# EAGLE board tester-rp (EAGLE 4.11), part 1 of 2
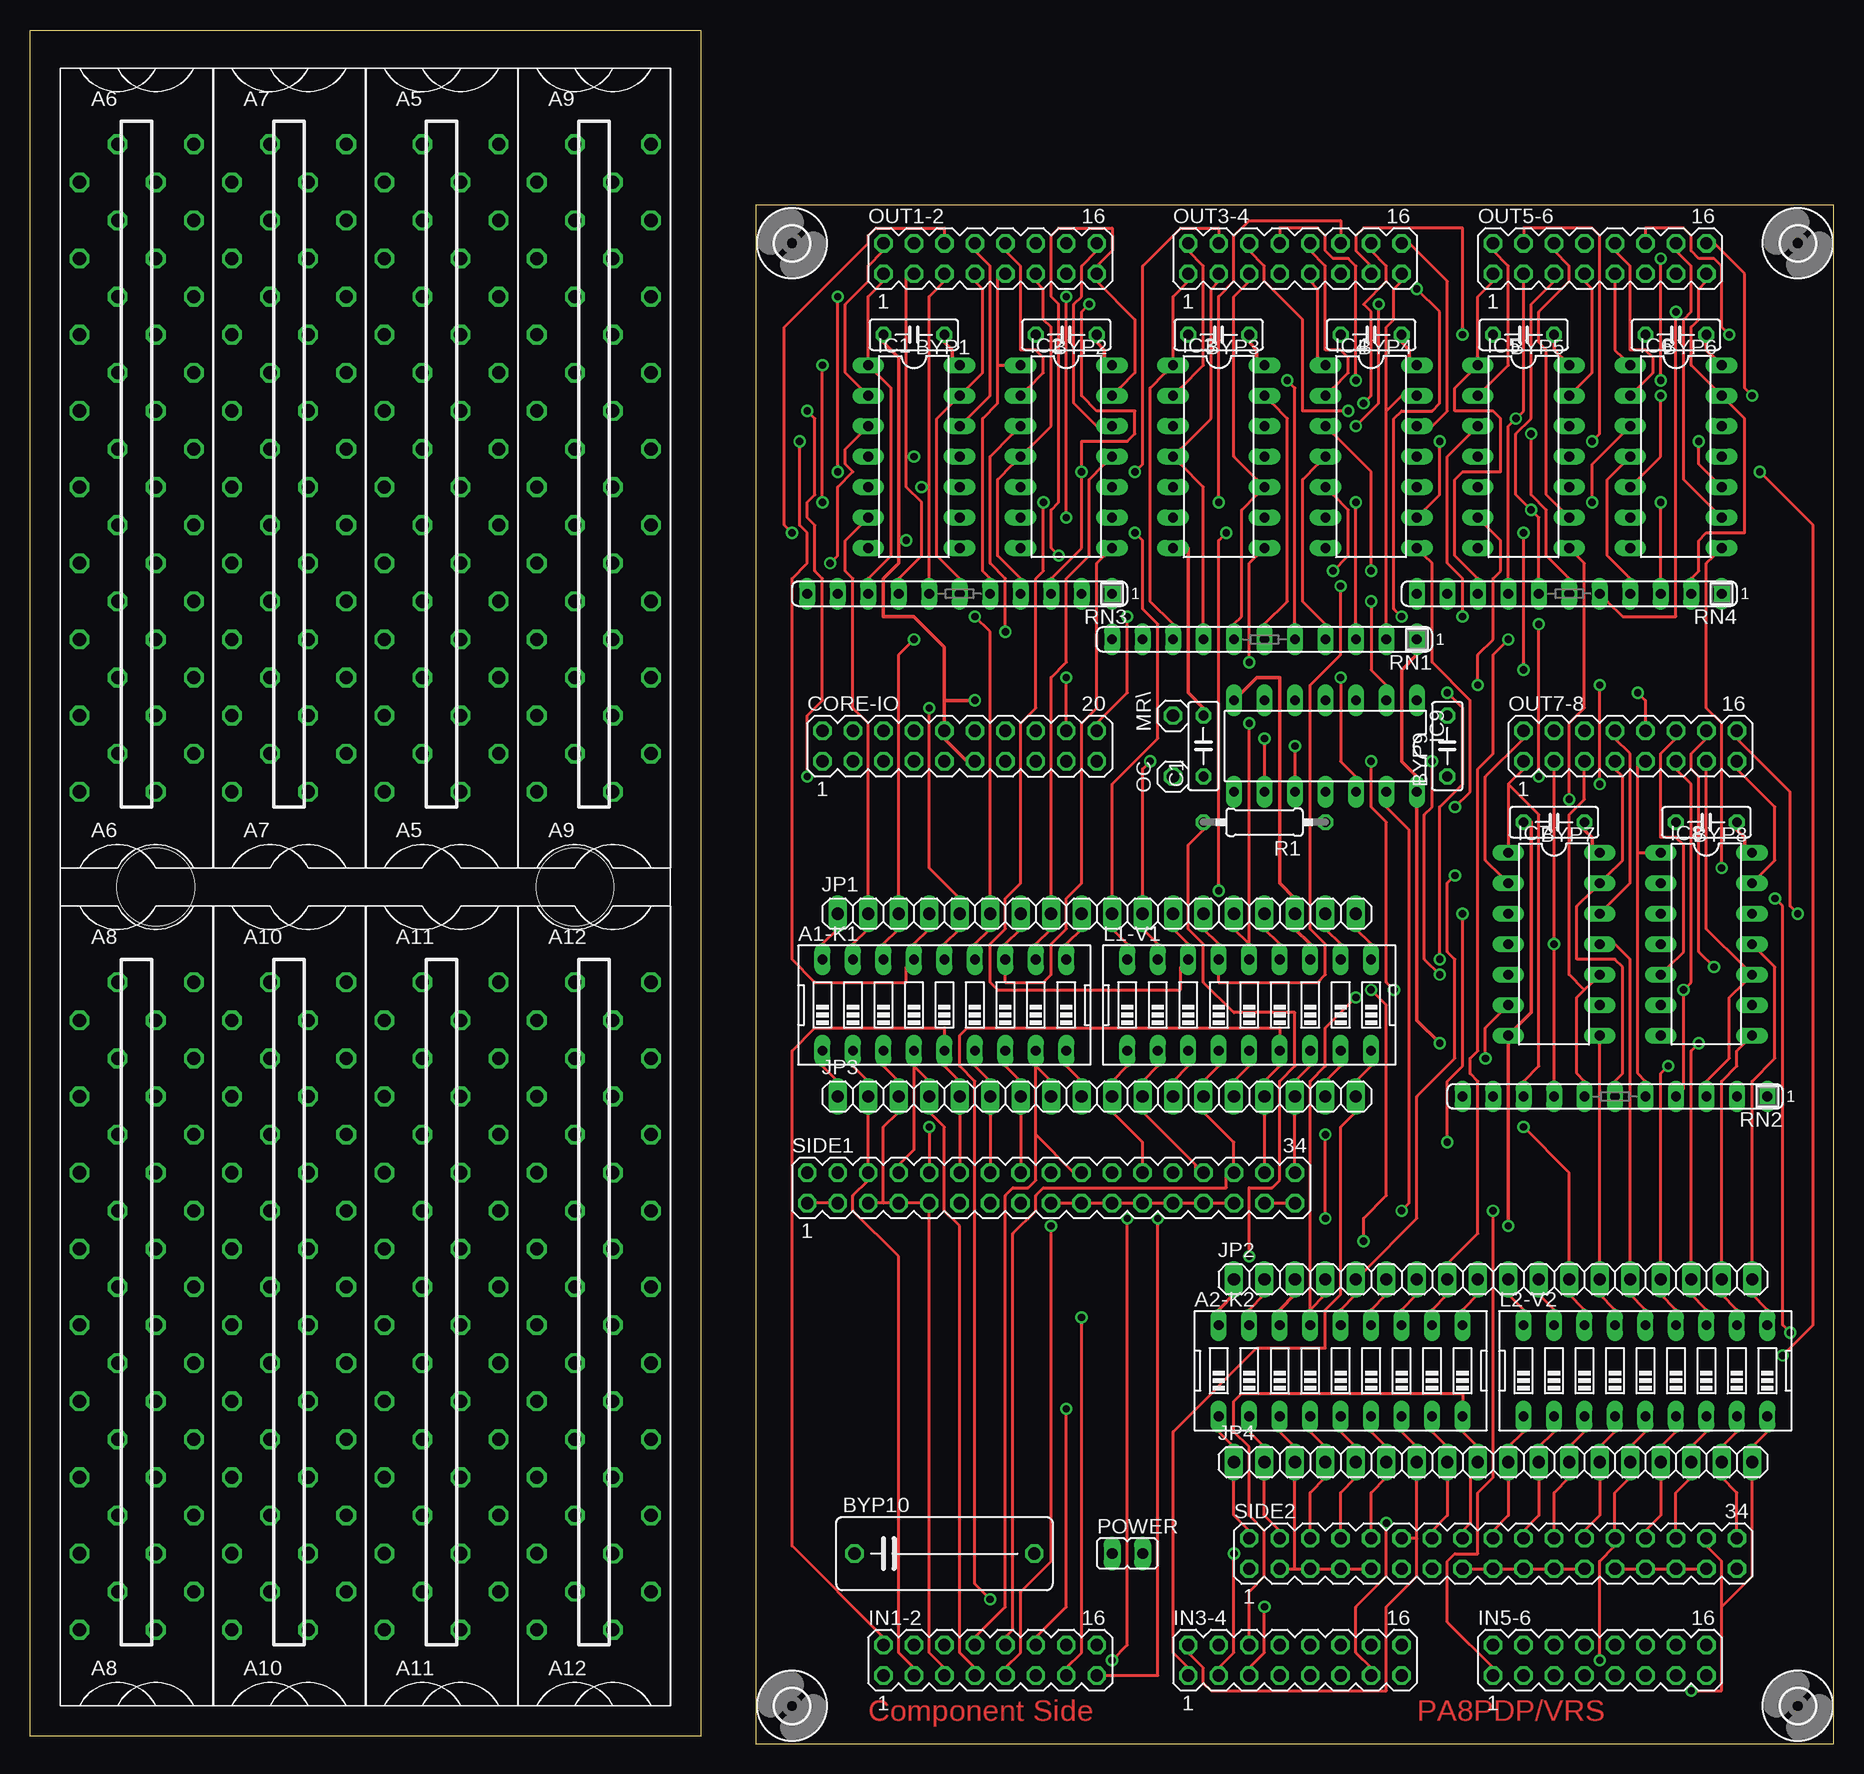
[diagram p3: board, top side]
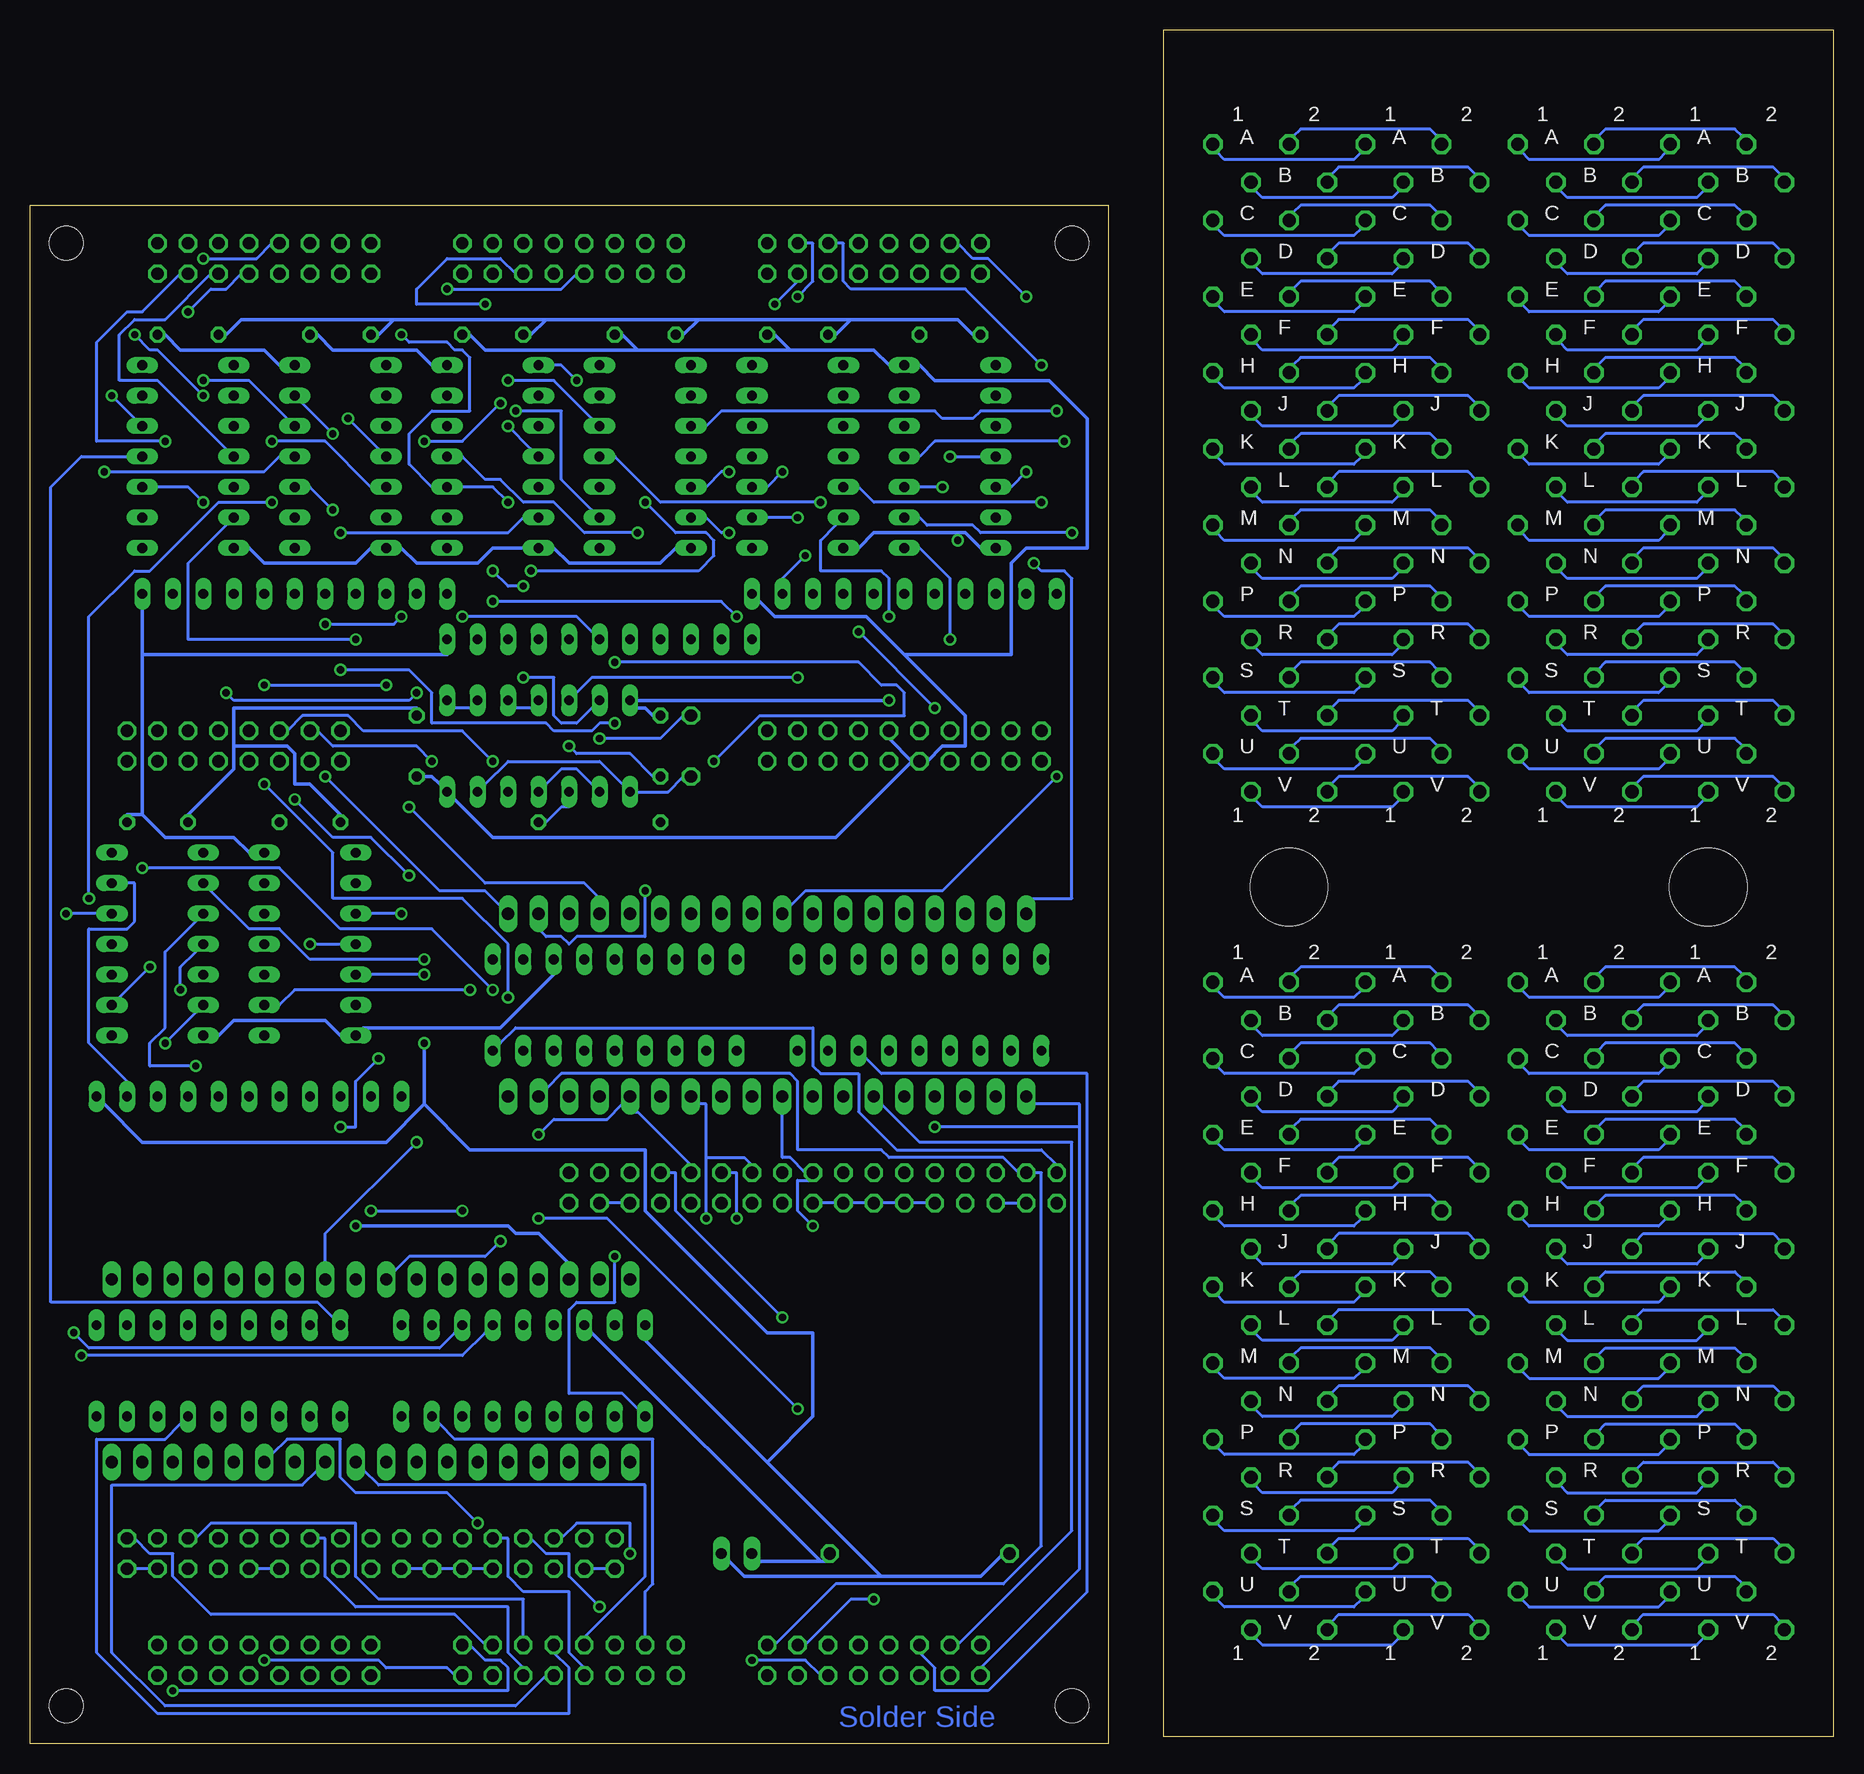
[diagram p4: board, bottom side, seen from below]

Size 150.33 x 142.86 mm. Coordinates in mm from the lower left corner, seen from the top.
Outline: 60.49,128.25 60.49,0 150.33,0 150.33,128.25 60.49,128.25
Outline: 55.88,0.62 0,0.62 0,142.86 55.88,142.86 55.88,0.62
Copper layers (1*16): Top 0.035mm / dielectric 1.5mm / Bottom 0.035mm
Design rules "olimex10mil": minimum track width 10mil, minimum drill 24mil, track to track 10mil, track to pad 10mil, pad to pad 10mil, via to via 10mil, smd to smd 10mil, copper to edge 40mil, drill to drill 10mil, minimum pad ring 10mil, minimum via ring 8mil, stop-mask expansion 0mil, vias tented up to drill 0mil, thermal gap 10mil
Net classes: 1 Power: width 0.305 mm, drill 0.305 mm

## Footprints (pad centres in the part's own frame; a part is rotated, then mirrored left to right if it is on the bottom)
EDG-09 = drill 0.813 long: 1 -10.16,-3.81; 2 -7.62,-3.81; 3 -5.08,-3.81; 4 -2.54,-3.81; 5 0,-3.81; 6 2.54,-3.81; 7 5.08,-3.81; 8 7.62,-3.81; 9 10.16,-3.81; 10 10.16,3.81; 11 7.62,3.81; 12 5.08,3.81; 13 2.54,3.81; 14 0,3.81; 15 -2.54,3.81; 16 -5.08,3.81; 17 -7.62,3.81; 18 -10.16,3.81
H807 = drill 1.092 octagon: A1 4.763,28.575; A2 -1.587,28.575; B1 1.587,25.4; B2 -4.763,25.4; C1 4.763,22.225; C2 -1.587,22.225; D1 1.587,19.05; D2 -4.763,19.05; E1 4.763,15.875; E2 -1.587,15.875; F1 1.587,12.7; F2 -4.763,12.7; H1 4.763,9.525; H2 -1.587,9.525; J1 1.587,6.35; J2 -4.763,6.35; K1 4.763,3.175; K2 -1.587,3.175; L1 1.587,0; L2 -4.763,0; M1 4.763,-3.175; M2 -1.587,-3.175; N1 1.587,-6.35; N2 -4.763,-6.35; P1 4.763,-9.525; P2 -1.587,-9.525; R1 1.587,-12.7; R2 -4.763,-12.7; S1 4.763,-15.875; S2 -1.587,-15.875; T1 1.587,-19.05; T2 -4.763,-19.05; U1 4.763,-22.225; U2 -1.587,-22.225; V1 1.587,-25.4; V2 -4.763,-25.4
C050-025X075 = drill 0.813 octagon: 1 -2.54,0; 2 2.54,0
C150-064X183 = drill 1.016 octagon: 1 -7.493,0; 2 7.493,0
MA10-2 = drill 1.016 octagon: 1 -11.43,-1.27; 2 -11.43,1.27; 3 -8.89,-1.27; 4 -8.89,1.27; 5 -6.35,-1.27; 6 -6.35,1.27; 7 -3.81,-1.27; 8 -3.81,1.27; 9 -1.27,-1.27; 10 -1.27,1.27; 11 1.27,-1.27; 12 1.27,1.27; 13 3.81,-1.27; 14 3.81,1.27; 15 6.35,-1.27; 16 6.35,1.27; 17 8.89,-1.27; 18 8.89,1.27; 19 11.43,-1.27; 20 11.43,1.27
DIL14 = drill 0.813 long: 1 -7.62,-3.81; 2 -5.08,-3.81; 3 -2.54,-3.81; 4 0,-3.81; 5 2.54,-3.81; 6 5.08,-3.81; 7 7.62,-3.81; 8 7.62,3.81; 9 5.08,3.81; 10 2.54,3.81; 11 0,3.81; 12 -2.54,3.81; 13 -5.08,3.81; 14 -7.62,3.81
MA08-2 = drill 1.016 octagon: 1 -8.89,-1.27; 2 -8.89,1.27; 3 -6.35,-1.27; 4 -6.35,1.27; 5 -3.81,-1.27; 6 -3.81,1.27; 7 -1.27,-1.27; 8 -1.27,1.27; 9 1.27,-1.27; 10 1.27,1.27; 11 3.81,-1.27; 12 3.81,1.27; 13 6.35,-1.27; 14 6.35,1.27; 15 8.89,-1.27; 16 8.89,1.27
1X18 = drill 1.016 long: 1 -21.59,0; 2 -19.05,0; 3 -16.51,0; 4 -13.97,0; 5 -11.43,0; 6 -8.89,0; 7 -6.35,0; 8 -3.81,0; 9 -1.27,0; 10 1.27,0; 11 3.81,0; 12 6.35,0; 13 8.89,0; 14 11.43,0; 15 13.97,0; 16 16.51,0; 17 19.05,0; 18 21.59,0
1X01 = drill 1.016 octagon: 1 0,0
JP1 = drill 0.914 long: 1 0,-1.27; 2 0,1.27
0207/10 = drill 0.813 octagon: 1 -5.08,0; 2 5.08,0
SIL11 = drill 0.813 long: 1 -12.7,0; 2 -10.16,0; 3 -7.62,0; 4 -5.08,0; 5 -2.54,0; 6 0,0; 7 2.54,0; 8 5.08,0; 9 7.62,0; 10 10.16,0; 11 12.7,0
MA17-2 = drill 1.016 octagon: 1 -20.32,-1.27; 2 -20.32,1.27; 3 -17.78,-1.27; 4 -17.78,1.27; 5 -15.24,-1.27; 6 -15.24,1.27; 7 -12.7,-1.27; 8 -12.7,1.27; 9 -10.16,-1.27; 10 -10.16,1.27; 11 -7.62,-1.27; 12 -7.62,1.27; 13 -5.08,-1.27; 14 -5.08,1.27; 15 -2.54,-1.27; 16 -2.54,1.27; 17 0,-1.27; 18 0,1.27; 19 2.54,-1.27; 20 2.54,1.27; 21 5.08,-1.27; 22 5.08,1.27; 23 7.62,-1.27; 24 7.62,1.27; 25 10.16,-1.27; 26 10.16,1.27; 27 12.7,-1.27; 28 12.7,1.27; 29 15.24,-1.27; 30 15.24,1.27; 31 17.78,-1.27; 32 17.78,1.27; 33 20.32,-1.27; 34 20.32,1.27
2,8 = hole 2.8: 0,0
CBLOCK = hole 6.452: 7.938,68.263; 42.862,68.263

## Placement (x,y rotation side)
A1-K1  A1-K1  [EDG-09]  76.2,61.58 0 top
A2-K2  A2-K2  [EDG-09]  109.22,31.1 0 top
A5  [H807]  34.29,104.76 0 top
A6  [H807]  8.89,104.76 0 top
A7  [H807]  21.59,104.76 0 top
A8  [H807]  8.89,34.91 0 top
A9  [H807]  46.99,104.76 0 top
A10  [H807]  21.59,34.91 0 top
A11  [H807]  34.29,34.91 0 top
A12  [H807]  46.99,34.91 0 top
BYP1  0.1uf  [C050-025X075]  73.66,117.46 180 top
BYP2  0.1uf  [C050-025X075]  86.36,117.46 180 top
BYP3  0.1uf  [C050-025X075]  99.06,117.46 180 top
BYP4  0.1uf  [C050-025X075]  111.76,117.46 180 top
BYP5  0.1uf  [C050-025X075]  124.46,117.46 180 top
BYP6  0.1uf  [C050-025X075]  137.16,117.46 180 top
BYP7  0.1uf  [C050-025X075]  127,76.82 180 top
BYP8  0.1uf  [C050-025X075]  139.7,76.82 180 top
BYP9  0.1uf  [C050-025X075]  118.11,83.17 90 top
BYP10  100uf 25V  [C150-064X183]  76.2,15.86 0 top
C1  0.1uf  [C050-025X075]  97.79,83.17 90 top
CORE-IO  [MA10-2]  77.47,83.17 0 top
IC1  74LS125N  [DIL14]  73.66,107.3 270 top
IC2  74LS125N  [DIL14]  86.36,107.3 270 top
IC3  74LS125N  [DIL14]  99.06,107.3 270 top
IC4  74LS125N  [DIL14]  111.76,107.3 270 top
IC5  74LS125N  [DIL14]  124.46,107.3 270 top
IC6  74LS125N  [DIL14]  137.16,107.3 270 top
IC7  74LS125N  [DIL14]  127,66.66 270 top
IC8  74LS125N  [DIL14]  139.7,66.66 270 top
IC9  74LS00N  [DIL14]  107.95,83.17 180 top
IN1-2  [MA08-2]  80.01,6.97 0 top
IN3-4  [MA08-2]  105.41,6.97 0 top
IN5-6  [MA08-2]  130.81,6.97 0 top
JP1  [1X18]  88.9,69.2 0 top
JP2  [1X18]  121.92,38.72 0 top
JP3  [1X18]  88.9,53.96 0 top
JP4  [1X18]  121.92,23.48 0 top
L1-V1  L1-V1  [EDG-09]  101.6,61.58 0 top
L2-V2  L2-V2  [EDG-09]  134.62,31.1 0 top
MR\  MR\  [1X01]  95.25,85.71 90 top
OC  OC  [1X01]  95.25,80.63 90 top
OUT1-2  [MA08-2]  80.01,123.81 0 top
OUT3-4  [MA08-2]  105.41,123.81 0 top
OUT5-6  [MA08-2]  130.81,123.81 0 top
OUT7-8  [MA08-2]  133.35,83.17 0 top
POWER  POWER  [JP1]  91.44,15.86 270 top
R1  1K  [0207/10]  102.87,76.82 180 top
RN1  [SIL11]  102.87,92.06 180 top
RN2  [SIL11]  132.08,53.96 180 top
RN3  [SIL11]  77.47,95.87 180 top
RN4  [SIL11]  128.27,95.87 180 top
SIDE1  [MA17-2]  85.09,46.34 0 top
SIDE2  [MA17-2]  121.92,15.86 0 top
U$1  [2,8]  63.5,3.16 270 top
U$2  [2,8]  147.32,3.16 270 top
U$3  [2,8]  147.32,125.08 270 top
U$4  [2,8]  63.5,125.08 270 top
U$5  [CBLOCK]  2.54,3.16 0 top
